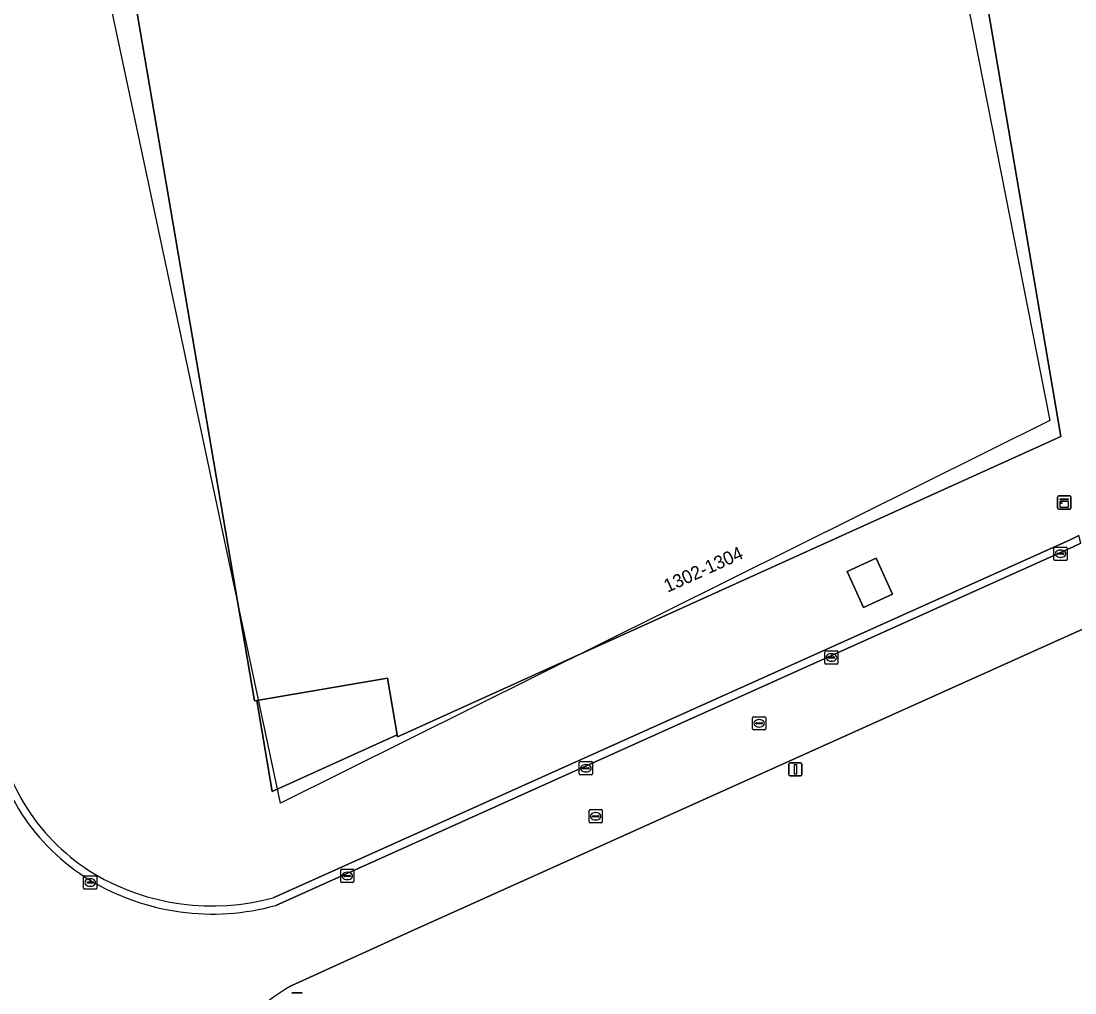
# Model space of a CAD drawing. Extents: x 154324 to 155744, y 382937 to 384188.
# Drawn here: x 154622.3 to 154702, y 383013.5 to 383087 of the extents above; entities that cross this region are included whole.
import ezdxf

# ---------------------------------------------------------------- set-up
doc = ezdxf.new("R2010")
doc.units = 0
for name, color, linetype in [('IMGEO_Berm_groen', 7, 'Continuous'), ('IMGEO_Erf', 7, 'Continuous'), ('IMGEO_Kast', 7, 'Continuous'), ('IMGEO_Kolk', 7, 'Continuous'), ('IMGEO_Lage_trafo', 7, 'Continuous'), ('IMGEO_Lichtmast', 7, 'Continuous'), ('IMGEO_Pand', 7, 'Continuous'), ('IMGEO_Pand_nummerreeks', 7, 'Continuous'), ('IMGEO_Pand_vergunning_verleend', 7, 'Continuous'), ('IMGEO_Rijbaan_lokaal_gesloten', 7, 'Continuous'), ('IMGEO_Rioolput', 7, 'Continuous')]:
    doc.layers.add(name, color=color, linetype=linetype)

msp = doc.modelspace()

# ---------------------------------------------------------------- linework, layer by layer
at = {"layer": 'IMGEO_Berm_groen'}
msp.add_lwpolyline([(154703.005, 383041.199), (154652.034, 383018.306), (154642.78, 383014.081)], dxfattribs=at)
msp.add_arc((154650.317, 383000.748), 15.316, 119.47976, 183.64109, dxfattribs=at)
at = {"layer": 'IMGEO_Erf'}
for points in [[(154678.388, 383188.109), (154700.956, 383055.605), (154650.777, 383032.891), (154650.751, 383033.044), (154641.287, 383028.766), (154640.116, 383035.626), (154639.963, 383035.6), (154623.689, 383130.917)], [(154641.36, 383020.718), (154644.058, 383021.92), (154701.677, 383047.796), (154702.336, 383048.109)]]:
    msp.add_lwpolyline(points, dxfattribs=at)
for points in [[(154688.229, 383043.667), (154686.033, 383042.676), (154684.802, 383045.401), (154686.999, 383046.392)], [(154650.021, 383037.317), (154640.116, 383035.626), (154641.287, 383028.766), (154650.751, 383033.044)]]:
    msp.add_lwpolyline(points, close=True, dxfattribs=at)
for centre, radius, start, end in [((154635.978, 383035.97), 15.721, 187.56064, 238.66174), ((154636.745, 383037.707), 17.605, 239.47001, 285.19734)]:
    msp.add_arc(centre, radius, start, end, dxfattribs=at)
at = {"layer": 'IMGEO_Kast'}
for p, q in [((154700.721, 383050.18), (154700.721, 383051.021)), ((154700.721, 383051.021), (154700.721, 383050.18)), ((154700.796, 383051.105), (154701.637, 383051.105)), ((154701.637, 383051.105), (154700.796, 383051.105)), ((154701.721, 383051.03), (154701.721, 383050.189)), ((154701.721, 383050.189), (154701.721, 383051.03)), ((154701.646, 383050.105), (154700.805, 383050.105)), ((154700.805, 383050.105), (154701.646, 383050.105))]:
    msp.add_line(p, q, dxfattribs=at)
for points in [[(154700.916, 383050.895), (154701.516, 383050.895), (154701.516, 383050.81), (154700.916, 383050.81), (154700.916, 383050.895)], [(154700.916, 383050.72), (154701.516, 383050.72), (154701.516, 383050.231), (154700.916, 383050.231), (154700.916, 383050.72)]]:
    msp.add_lwpolyline(points, dxfattribs=at)
msp.add_circle((154701, 383050.569), 0.0377, dxfattribs=at)
for centre, start, end in [((154700.799, 383051.027), 92.4484, 184.28452), ((154700.799, 383051.027), 92.4484, 184.28452), ((154701.643, 383051.027), 2.4484, 94.28452), ((154701.643, 383051.027), 2.4484, 94.28452), ((154700.799, 383050.183), 182.4484, 274.28452), ((154700.799, 383050.183), 182.4484, 274.28452), ((154701.643, 383050.183), 272.4484, 4.28452), ((154701.643, 383050.183), 272.4484, 4.28452)]:
    msp.add_arc(centre, 0.0779, start, end, dxfattribs=at)
at = {"layer": 'IMGEO_Kolk'}
for p, q in [((154700.442, 383046.309), (154700.442, 383047.161)), ((154700.517, 383047.235), (154701.369, 383047.235)), ((154700.701, 383046.729), (154700.701, 383046.741)), ((154701.139, 383046.692), (154700.741, 383046.692)), ((154700.744, 383046.778), (154701.142, 383046.778)), ((154700.93, 383047.015), (154700.955, 383047.015)), ((154701.185, 383046.741), (154701.185, 383046.729)), ((154701.443, 383047.161), (154701.443, 383046.309)), ((154701.369, 383046.235), (154700.517, 383046.235)), ((154700.953, 383046.455), (154700.928, 383046.455)), ((154683.099, 383038.464), (154683.099, 383039.316)), ((154683.174, 383039.39), (154684.026, 383039.39)), ((154683.358, 383038.884), (154683.358, 383038.896)), ((154683.796, 383038.847), (154683.398, 383038.847)), ((154683.401, 383038.933), (154683.799, 383038.933)), ((154683.61, 383038.61), (154683.585, 383038.61)), ((154683.587, 383039.17), (154683.612, 383039.17)), ((154683.842, 383038.896), (154683.842, 383038.884)), ((154684.1, 383039.316), (154684.1, 383038.464)), ((154684.026, 383038.39), (154683.174, 383038.39)), ((154664.525, 383030.086), (154664.525, 383030.938)), ((154664.6, 383031.012), (154665.452, 383031.012)), ((154665.013, 383030.792), (154665.038, 383030.792)), ((154665.526, 383030.938), (154665.526, 383030.086)), ((154665.452, 383030.012), (154664.6, 383030.012)), ((154664.784, 383030.506), (154664.784, 383030.518)), ((154665.222, 383030.469), (154664.824, 383030.469)), ((154664.827, 383030.555), (154665.225, 383030.555)), ((154665.036, 383030.232), (154665.011, 383030.232)), ((154665.268, 383030.518), (154665.268, 383030.506)), ((154646.471, 383021.945), (154646.471, 383022.797)), ((154646.546, 383022.871), (154647.398, 383022.871)), ((154647.472, 383022.797), (154647.472, 383021.945)), ((154627.018, 383021.446), (154627.018, 383022.298)), ((154627.093, 383022.372), (154627.945, 383022.372)), ((154627.277, 383021.866), (154627.277, 383021.878)), ((154627.32, 383021.915), (154627.718, 383021.915)), ((154627.506, 383022.152), (154627.531, 383022.152)), ((154627.761, 383021.878), (154627.761, 383021.866)), ((154628.019, 383022.298), (154628.019, 383021.446)), ((154647.398, 383021.871), (154646.546, 383021.871)), ((154646.73, 383022.365), (154646.73, 383022.377)), ((154647.168, 383022.328), (154646.77, 383022.328)), ((154646.773, 383022.414), (154647.171, 383022.414)), ((154646.982, 383022.091), (154646.957, 383022.091)), ((154646.959, 383022.651), (154646.984, 383022.651)), ((154647.214, 383022.377), (154647.214, 383022.365)), ((154627.945, 383021.372), (154627.093, 383021.372)), ((154627.715, 383021.829), (154627.317, 383021.829)), ((154627.529, 383021.592), (154627.504, 383021.592))]:
    msp.add_line(p, q, dxfattribs=at)
for points in [[(154700.442, 383046.309), (154700.442, 383047.161)], [(154700.517, 383047.235), (154701.369, 383047.235)], [(154701.443, 383047.161), (154701.443, 383046.309)], [(154701.369, 383046.235), (154700.517, 383046.235)], [(154683.099, 383038.464), (154683.099, 383039.316)], [(154683.174, 383039.39), (154684.026, 383039.39)], [(154684.1, 383039.316), (154684.1, 383038.464)], [(154684.026, 383038.39), (154683.174, 383038.39)], [(154664.525, 383030.086), (154664.525, 383030.938)], [(154664.6, 383031.012), (154665.452, 383031.012)], [(154665.526, 383030.938), (154665.526, 383030.086)], [(154665.452, 383030.012), (154664.6, 383030.012)], [(154646.471, 383021.945), (154646.471, 383022.797)], [(154646.546, 383022.871), (154647.398, 383022.871)], [(154647.472, 383022.797), (154647.472, 383021.945)], [(154627.018, 383021.446), (154627.018, 383022.298)], [(154627.093, 383022.372), (154627.945, 383022.372)], [(154628.019, 383022.298), (154628.019, 383021.446)], [(154647.398, 383021.871), (154646.546, 383021.871)], [(154627.945, 383021.372), (154627.093, 383021.372)]]:
    msp.add_lwpolyline(points, dxfattribs=at)
for centre, radius, start, end in [((154700.519, 383047.159), 0.0765, 91.55205, 178.44795), ((154700.519, 383047.159), 0.0765, 91.55205, 178.44795), ((154700.741, 383046.738), 0.0403, 85.87752, 175.75265), ((154700.738, 383046.728), 0.0366, 178.93798, 274.71019), ((154701.142, 383046.735), 0.043, 264.86636, 352.45326), ((154701.146, 383046.74), 0.0386, 1.73085, 96.63898), ((154701.367, 383047.159), 0.0765, 1.55205, 88.44795), ((154701.367, 383047.159), 0.0765, 1.55205, 88.44795), ((154700.519, 383046.311), 0.0765, 181.55205, 268.44795), ((154700.519, 383046.311), 0.0765, 181.55205, 268.44795), ((154701.367, 383046.311), 0.0765, 271.55205, 358.44795), ((154701.367, 383046.311), 0.0765, 271.55205, 358.44795), ((154683.176, 383039.314), 0.0765, 91.55205, 178.44795), ((154683.176, 383039.314), 0.0765, 91.55205, 178.44795), ((154683.398, 383038.893), 0.0403, 85.87752, 175.75265), ((154683.395, 383038.883), 0.0366, 178.93798, 274.71019), ((154683.799, 383038.89), 0.043, 264.86636, 352.45326), ((154683.803, 383038.895), 0.0386, 1.73085, 96.63898), ((154684.024, 383039.314), 0.0765, 1.55205, 88.44795), ((154684.024, 383039.314), 0.0765, 1.55205, 88.44795), ((154683.176, 383038.466), 0.0765, 181.55205, 268.44795), ((154683.176, 383038.466), 0.0765, 181.55205, 268.44795), ((154684.024, 383038.466), 0.0765, 271.55205, 358.44795), ((154684.024, 383038.466), 0.0765, 271.55205, 358.44795), ((154664.602, 383030.936), 0.0765, 91.55205, 178.44795), ((154664.602, 383030.936), 0.0765, 91.55205, 178.44795), ((154665.45, 383030.936), 0.0765, 1.55205, 88.44795), ((154665.45, 383030.936), 0.0765, 1.55205, 88.44795), ((154664.602, 383030.088), 0.0765, 181.55205, 268.44795), ((154664.602, 383030.088), 0.0765, 181.55205, 268.44795), ((154664.824, 383030.515), 0.0403, 85.87752, 175.75265), ((154664.821, 383030.505), 0.0366, 178.93798, 274.71019), ((154665.225, 383030.512), 0.043, 264.86636, 352.45326), ((154665.229, 383030.517), 0.0386, 1.73085, 96.63898), ((154665.45, 383030.088), 0.0765, 271.55205, 358.44795), ((154665.45, 383030.088), 0.0765, 271.55205, 358.44795), ((154646.548, 383022.795), 0.0765, 91.55205, 178.44795), ((154646.548, 383022.795), 0.0765, 91.55205, 178.44795), ((154647.396, 383022.795), 0.0765, 1.55205, 88.44795), ((154647.396, 383022.795), 0.0765, 1.55205, 88.44795), ((154627.095, 383022.296), 0.0765, 91.55205, 178.44795), ((154627.095, 383022.296), 0.0765, 91.55205, 178.44795), ((154627.317, 383021.875), 0.0403, 85.87752, 175.75265), ((154627.314, 383021.865), 0.0366, 178.93798, 274.71019), ((154627.718, 383021.872), 0.043, 264.86636, 352.45326), ((154627.722, 383021.877), 0.0386, 1.73085, 96.63898), ((154627.943, 383022.296), 0.0765, 1.55205, 88.44795), ((154627.943, 383022.296), 0.0765, 1.55205, 88.44795), ((154646.548, 383021.947), 0.0765, 181.55205, 268.44795), ((154646.548, 383021.947), 0.0765, 181.55205, 268.44795), ((154646.77, 383022.374), 0.0403, 85.87752, 175.75265), ((154646.767, 383022.364), 0.0366, 178.93798, 274.71019), ((154647.171, 383022.371), 0.043, 264.86636, 352.45326), ((154647.175, 383022.376), 0.0386, 1.73085, 96.63898), ((154647.396, 383021.947), 0.0765, 271.55205, 358.44795), ((154647.396, 383021.947), 0.0765, 271.55205, 358.44795), ((154627.095, 383021.448), 0.0765, 181.55205, 268.44795), ((154627.095, 383021.448), 0.0765, 181.55205, 268.44795), ((154627.943, 383021.448), 0.0765, 271.55205, 358.44795), ((154627.943, 383021.448), 0.0765, 271.55205, 358.44795)]:
    msp.add_arc(centre, radius, start, end, dxfattribs=at)
for centre, major_axis, ratio, start_param, end_param in [((154700.929, 383046.735), (-0.387, 0.002), 0.722429, 4.712389, 7.853982), ((154700.954, 383046.735), (-0.39, 0.002), 0.717154, 1.570796, 4.712389), ((154683.586, 383038.89), (-0.387, 0.002), 0.722429, 4.712389, 7.853982), ((154683.611, 383038.89), (-0.39, 0.002), 0.717154, 1.570796, 4.712389), ((154665.012, 383030.512), (-0.387, 0.002), 0.722429, 4.712389, 7.853982), ((154665.037, 383030.512), (-0.39, 0.002), 0.717154, 1.570796, 4.712389), ((154627.505, 383021.872), (-0.387, 0.002), 0.722429, 4.712389, 7.853982), ((154627.53, 383021.872), (-0.39, 0.002), 0.717154, 1.570796, 4.712389), ((154646.958, 383022.371), (-0.387, 0.002), 0.722429, 4.712389, 7.853982), ((154646.983, 383022.371), (-0.39, 0.002), 0.717154, 1.570796, 4.712389)]:
    msp.add_ellipse(centre, major_axis=major_axis, ratio=ratio, start_param=start_param, end_param=end_param, dxfattribs=at)
at = {"layer": 'IMGEO_Lage_trafo'}
msp.add_lwpolyline([(154686.999, 383046.392), (154684.802, 383045.401), (154686.033, 383042.676), (154688.229, 383043.667)], close=True, dxfattribs=at)
at = {"layer": 'IMGEO_Lichtmast'}
for p, q in [((154680.384, 383030.033), (154680.384, 383030.833)), ((154680.384, 383030.833), (154680.384, 383030.033)), ((154680.484, 383030.933), (154681.274, 383030.933)), ((154681.274, 383030.933), (154680.484, 383030.933)), ((154681.374, 383030.833), (154681.374, 383030.033)), ((154681.374, 383030.033), (154681.374, 383030.833)), ((154681.274, 383029.933), (154680.484, 383029.933)), ((154680.484, 383029.933), (154681.274, 383029.933)), ((154642.774, 383013.525), (154643.564, 383013.525)), ((154643.564, 383013.525), (154642.774, 383013.525))]:
    msp.add_line(p, q, dxfattribs=at)
msp.add_lwpolyline([(154680.804, 383030.808), (154680.954, 383030.808), (154680.954, 383030.058), (154680.804, 383030.058), (154680.804, 383030.808)], dxfattribs=at)
for centre, start, end in [((154680.484, 383030.833), 90, 180), ((154680.484, 383030.833), 90, 180), ((154681.274, 383030.833), 0, 90), ((154681.274, 383030.833), 360, 90), ((154680.484, 383030.033), 180, 270), ((154680.484, 383030.033), 180, 270), ((154681.274, 383030.033), 270, 0), ((154681.274, 383030.033), 270, 0)]:
    msp.add_arc(centre, 0.1, start, end, dxfattribs=at)
at = {"layer": 'IMGEO_Pand'}
msp.add_lwpolyline([(154623.689, 383130.917), (154639.963, 383035.6), (154640.116, 383035.626), (154650.021, 383037.317), (154650.751, 383033.044), (154650.777, 383032.891), (154700.956, 383055.605), (154678.388, 383188.109)], dxfattribs=at)
at = {"layer": 'IMGEO_Pand_vergunning_verleend'}
msp.add_lwpolyline([(154584.715, 383256.808), (154657.955, 383270.711), (154700.131, 383056.801), (154641.926, 383027.883), (154620.799, 383127.072), (154608.343, 383124.842)], close=True, dxfattribs=at)
at = {"layer": 'IMGEO_Rijbaan_lokaal_gesloten'}
for points in [[(154641.566, 383020.143), (154644.31, 383021.367), (154701.889, 383047.258), (154702.471, 383047.534), (154702.336, 383048.109), (154701.677, 383047.796), (154644.058, 383021.92), (154641.36, 383020.718)], [(154702.471, 383047.534), (154701.889, 383047.258), (154644.31, 383021.367), (154641.566, 383020.143)], [(154642.78, 383014.081), (154652.034, 383018.306), (154703.005, 383041.199)]]:
    msp.add_lwpolyline(points, dxfattribs=at)
for centre, radius, start, end in [((154635.978, 383035.97), 15.721, 187.56064, 238.66174), ((154635.98, 383035.963), 16.291, 187.58711, 238.53193), ((154635.98, 383035.963), 16.291, 187.58711, 238.53193), ((154636.759, 383037.485), 17.996, 238.9474, 285.49324), ((154636.759, 383037.485), 17.996, 238.9474, 285.49324), ((154636.745, 383037.707), 17.605, 239.47001, 285.19734), ((154650.317, 383000.748), 15.316, 119.47976, 183.64109)]:
    msp.add_arc(centre, radius, start, end, dxfattribs=at)
at = {"layer": 'IMGEO_Rioolput'}
for p, q in [((154677.635, 383033.484), (154677.635, 383034.336)), ((154677.71, 383034.41), (154678.562, 383034.41)), ((154677.894, 383033.904), (154677.894, 383033.916)), ((154678.332, 383033.867), (154677.934, 383033.867)), ((154677.937, 383033.953), (154678.335, 383033.953)), ((154678.123, 383034.19), (154678.148, 383034.19)), ((154678.378, 383033.916), (154678.378, 383033.904)), ((154678.636, 383034.336), (154678.636, 383033.484)), ((154678.562, 383033.41), (154677.71, 383033.41)), ((154678.146, 383033.63), (154678.121, 383033.63)), ((154665.266, 383026.456), (154665.266, 383027.308)), ((154665.341, 383027.382), (154666.193, 383027.382)), ((154665.525, 383026.876), (154665.525, 383026.888)), ((154665.963, 383026.839), (154665.565, 383026.839)), ((154665.568, 383026.925), (154665.966, 383026.925)), ((154665.754, 383027.162), (154665.779, 383027.162)), ((154666.009, 383026.888), (154666.009, 383026.876)), ((154666.267, 383027.308), (154666.267, 383026.456)), ((154666.193, 383026.382), (154665.341, 383026.382)), ((154665.777, 383026.602), (154665.752, 383026.602))]:
    msp.add_line(p, q, dxfattribs=at)
for points in [[(154677.635, 383033.484), (154677.635, 383034.336)], [(154677.71, 383034.41), (154678.562, 383034.41)], [(154678.636, 383034.336), (154678.636, 383033.484)], [(154678.562, 383033.41), (154677.71, 383033.41)], [(154665.266, 383026.456), (154665.266, 383027.308)], [(154665.341, 383027.382), (154666.193, 383027.382)], [(154666.267, 383027.308), (154666.267, 383026.456)], [(154666.193, 383026.382), (154665.341, 383026.382)]]:
    msp.add_lwpolyline(points, dxfattribs=at)
for centre, radius, start, end in [((154677.712, 383034.334), 0.0765, 91.55205, 178.44795), ((154677.712, 383034.334), 0.0765, 91.55205, 178.44795), ((154677.934, 383033.913), 0.0403, 85.87752, 175.75265), ((154677.931, 383033.903), 0.0366, 178.93798, 274.71019), ((154678.335, 383033.91), 0.043, 264.86636, 352.45326), ((154678.339, 383033.915), 0.0386, 1.73085, 96.63898), ((154678.56, 383034.334), 0.0765, 1.55205, 88.44795), ((154678.56, 383034.334), 0.0765, 1.55205, 88.44795), ((154677.712, 383033.486), 0.0765, 181.55205, 268.44795), ((154677.712, 383033.486), 0.0765, 181.55205, 268.44795), ((154678.56, 383033.486), 0.0765, 271.55205, 358.44795), ((154678.56, 383033.486), 0.0765, 271.55205, 358.44795), ((154665.343, 383027.306), 0.0765, 91.55205, 178.44795), ((154665.343, 383027.306), 0.0765, 91.55205, 178.44795), ((154665.565, 383026.885), 0.0403, 85.87752, 175.75265), ((154665.562, 383026.875), 0.0366, 178.93798, 274.71019), ((154665.966, 383026.882), 0.043, 264.86636, 352.45326), ((154665.97, 383026.887), 0.0386, 1.73085, 96.63898), ((154666.191, 383027.306), 0.0765, 1.55205, 88.44795), ((154666.191, 383027.306), 0.0765, 1.55205, 88.44795), ((154665.343, 383026.458), 0.0765, 181.55205, 268.44795), ((154665.343, 383026.458), 0.0765, 181.55205, 268.44795), ((154666.191, 383026.458), 0.0765, 271.55205, 358.44795), ((154666.191, 383026.458), 0.0765, 271.55205, 358.44795)]:
    msp.add_arc(centre, radius, start, end, dxfattribs=at)
for centre, major_axis, ratio, start_param, end_param in [((154678.122, 383033.91), (-0.387, 0.002), 0.722429, 4.712389, 7.853982), ((154678.147, 383033.91), (-0.39, 0.002), 0.717154, 1.570796, 4.712389), ((154665.753, 383026.882), (-0.387, 0.002), 0.722429, 4.712389, 7.853982), ((154665.778, 383026.882), (-0.39, 0.002), 0.717154, 1.570796, 4.712389)]:
    msp.add_ellipse(centre, major_axis=major_axis, ratio=ratio, start_param=start_param, end_param=end_param, dxfattribs=at)

# ---------------------------------------------------------------- texts
at = {"layer": 'IMGEO_Pand_nummerreeks'}
msp.add_text('1302-1304', height=1, rotation=24.35644, dxfattribs=at).set_placement((154671.197, 383043.78))

doc.saveas('drawing.dxf')
